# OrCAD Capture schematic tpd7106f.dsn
size B
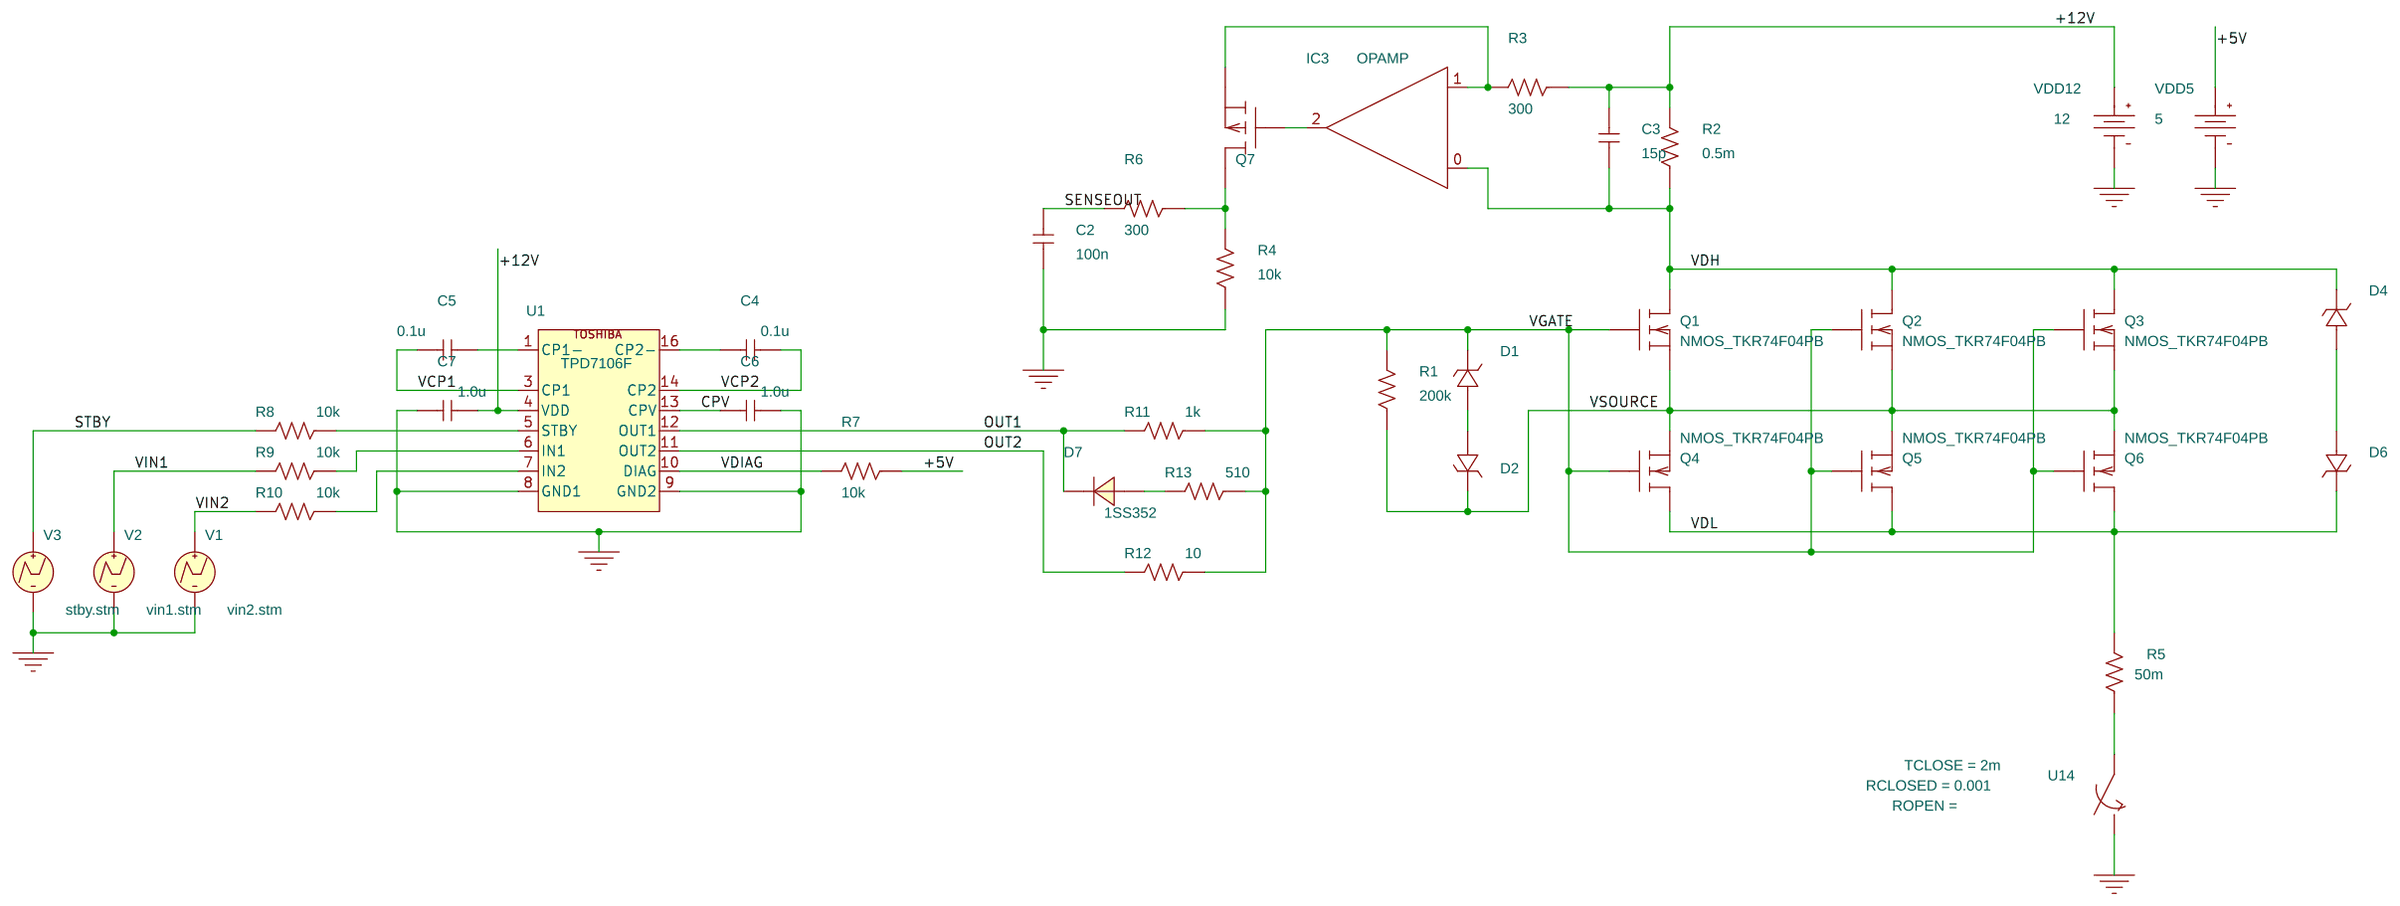
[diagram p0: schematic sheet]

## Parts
C2  100n  [RAD/CK05]
C3  15p  [RAD/CK05]
C4  0.1u  [RAD/CK05]
C5  0.1u  [RAD/CK05]
C6  1.0u  [RAD/CK05]
C7  1.0u  [RAD/CK05]
D1  CRZ16
D2  CRZ16
D4  CMZ27
D6  CMZ27
D7  1SS352
IC3  OPAMP
Q1  NMOS_TKR74F04PB
Q2  NMOS_TKR74F04PB
Q3  NMOS_TKR74F04PB
Q4  NMOS_TKR74F04PB
Q5  NMOS_TKR74F04PB
Q6  NMOS_TKR74F04PB
Q7  MbreakP3
R1  200k  [AX/RC05]
R2  0.5m  [AX/RC05]
R3  300  [AX/RC05]
R4  10k  [AX/RC05]
R5  50m  [AX/RC05]
R6  300  [AX/RC05]
R7  10k  [AX/RC05]
R8  10k  [AX/RC05]
R9  10k  [AX/RC05]
R10  10k  [AX/RC05]
R11  1k  [AX/RC05]
R12  10  [AX/RC05]
R13  510  [AX/RC05]
U1  TPD7106F
U14  Switch Closes at T
V1  VPWL_FILE
V2  VPWL_FILE
V3  VPWL_FILE
VDD5  VDC
VDD12  VDC

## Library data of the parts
C2-C7 = C
D1 D2 = CRZ16
D4 D6 = CMZ27
D7 = 1SS352
IC3 = OPAMP
Q1-Q6 = NMOS_TKR74F04PB
Q7 = MbreakP3
R1-R13 = R
U1 = TPD7106F
U14 = Sw_tClose: RCLOSED: 0.001; TCLOSE: 2m
V1 = VPWL_FILE: FILE: vin2.stm
V2 = VPWL_FILE: FILE: vin1.stm
V3 = VPWL_FILE: FILE: stby.stm
VDD5 = VDC: DC: 5
VDD12 = VDC: DC: 12

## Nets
+5V: R7.1 VDD5.0(+)
+12V: C3.2 C7.2 R2.2 R3.1 U1.4(VDD) VDD12.0(+)
VIN1: R9.2 V2.1(+)
VIN2: R10.2 V1.1(+)
0: C2.1 C6.2 C7.1 R4.1 U1.8(GND1) U1.9(GND2) U14.2 V1.2(-) V2.2(-) V3.2(-) VDD5.1(-) VDD12.1(-)
CPV: C6.1 U1.13(CPV)
OUT1: D7.2 R11.2 U1.12(OUT1)
OUT2: R12.2 U1.11(OUT2)
SENSEOUT: C2.2 R6.2
STBY: R8.2 V3.1(+)
VCP1: C5.2 U1.3(CP1)
VCP2: C4.1 U1.14(CP2)
VDH: C3.1 D4.1(2) IC3.0(+) Q1.1(d) Q2.1(d) Q3.1(d) R2.1
VDIAG: R7.2 U1.10(DIAG)
VDL: D6.1(2) Q4.1(d) Q5.1(d) Q6.1(d) R5.2
VGATE: D1.1(2) Q1.3(g) Q2.3(g) Q3.3(g) Q4.3(g) Q5.3(g) Q6.3(g) R1.2 R11.1 R12.1 R13.1
VSOURCE: D2.1(2) Q1.5(s) Q2.5(s) Q3.5(s) Q4.5(s) Q5.5(s) Q6.5(s) R1.1
N8016061: D1.0(1) D2.0(1)
N8016945: R5.1 U14.1
N8017141: IC3.1(-) Q7.1(s) R3.2
N8017216: IC3.2(OUT) Q7.0(g)
N8017236: Q7.2(d) R4.2 R6.1
N8017412: C4.2 U1.16(CP2-)
N8017431: C5.1 U1.1(CP1-)
N8017848: R8.1 U1.5(STBY)
N8017852: R9.1 U1.6(IN1)
N8017864: R10.1 U1.7(IN2)
N8020748: D4.0(1) D6.0(1)
N8022853: D7.1 R13.2
